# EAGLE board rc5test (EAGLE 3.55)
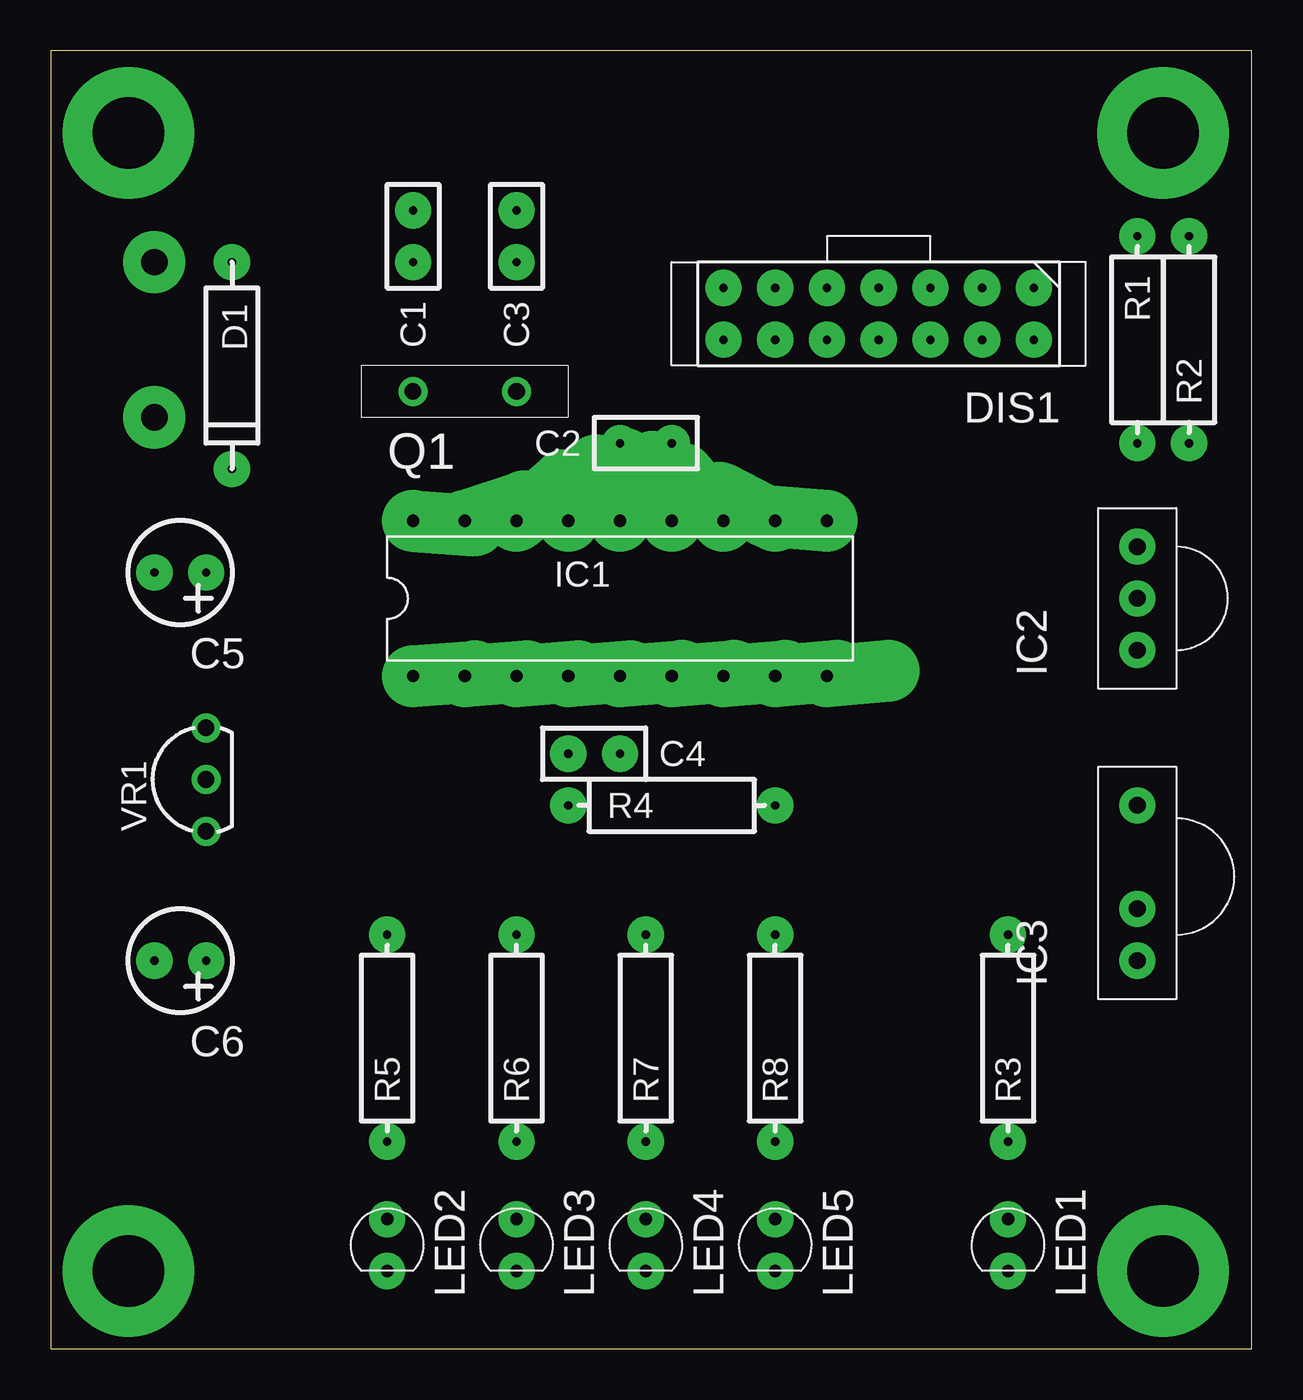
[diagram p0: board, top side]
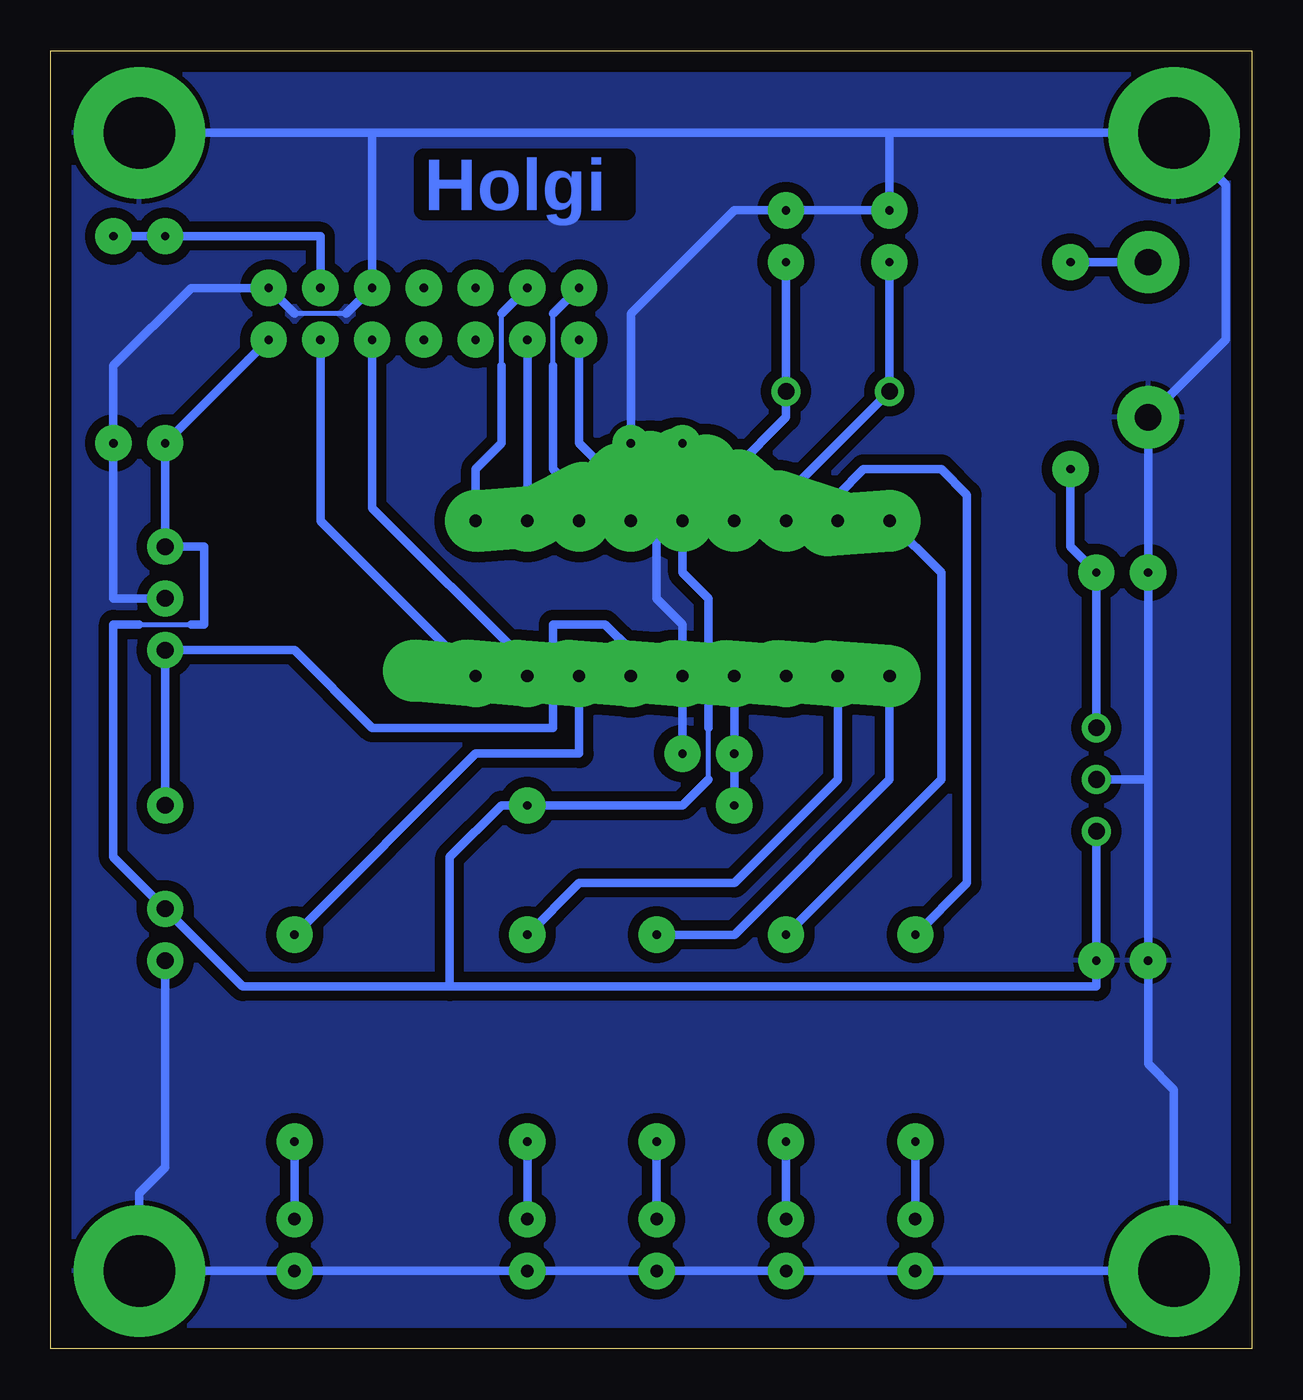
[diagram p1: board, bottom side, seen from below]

Size 58.95 x 63.71 mm. Coordinates in mm from the lower left corner, seen from the top.
Outline: 0,0 58.95,0 58.95,63.71 0,63.71 0,0
Copper layers used: Bottom

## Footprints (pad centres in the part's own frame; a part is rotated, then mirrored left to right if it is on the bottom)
RM2,5 = drill 0.406 pad 1.778 round:  0,0;  2.54,0
KO01 = drill 0.406 pad 1.778 round:  0,0;  2.54,0
O04 = drill 0.406 pad 1.778 round:  0,0;  10.16,0
7 = drill 0.406 pad 1.778 round:  0,0;  2.54,0;  5.08,0;  7.62,0;  10.16,0;  10.16,2.54;  7.62,2.54;  5.08,2.54;  2.54,2.54;  0,2.54;  12.7,0;  12.7,2.54;  15.24,0;  15.24,2.54
L-18B = drill 0.61 pad 3.048 offset:  0,0;  2.54,0;  15.24,0;  17.78,0;  5.08,0;  7.62,0;  12.7,0;  10.16,0;  20.32,0;  20.32,7.62;  17.78,7.62;  15.24,7.62;  12.7,7.62;  10.16,7.62;  7.62,7.62;  5.08,7.62;  2.54,7.62;  0,7.62
OP1836 = drill 0.813 pad 1.778 round:  0,0;  2.54,0;  5.08,0
REC = drill 0.813 pad 1.778 round:  0,0;  2.54,0;  7.62,0
D_3MM = drill 0.61 pad 1.778 round:  0,0;  2.54,0
GEL = drill 1.295 pad 3.048 round:  0,0
ARZ_ST = drill 0.813 pad 1.422 round:  0,0;  5.08,0
S04 = drill 0.406 pad 1.778 round:  0,0;  10.16,0
HRUNG = drill 3.505 pad 6.452 round:  0,0
92-B = drill 0.813 pad 1.422 round:  -2.54,0;  2.54,0;  0,0

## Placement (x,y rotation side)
C1  27p  [RM2,5]  17.78,55.88 270 top
C2  100n  [RM2,5]  30.48,44.45 180 top
C3  27p  [RM2,5]  22.86,55.88 270 top
C4  100n  [RM2,5]  25.4,29.21 0 top
C5  100u  [KO01]  7.62,38.1 180 top
C6  47u  [KO01]  7.62,19.05 180 top
D1  1N4148  [O04]  8.89,53.34 270 top
DIS1  LCD  [7]  48.26,52.07 180 top
IC1  16F84P  [L-18B]  17.78,33.02 0 top
IC2  TSOP1836  [OP1836]  53.34,34.29 90 top
IC3  TSOP1736  [REC]  53.34,19.05 90 top
LED1  Receive  [D_3MM]  46.99,6.35 270 top
LED2  COM4  [D_3MM]  16.51,6.35 270 top
LED3  COM5  [D_3MM]  22.86,6.35 270 top
LED4  COM6  [D_3MM]  29.21,6.35 270 top
LED5  COM7  [D_3MM]  35.56,6.35 270 top
N1  +  [GEL]  5.08,53.34 0 top
N2  -  [GEL]  5.08,45.72 0 top
Q1  4MHz  [ARZ_ST]  17.78,46.99 0 top
R1  12k  [S04]  53.34,54.61 270 top
R2  1k  [S04]  55.88,44.45 90 top
R3  270  [S04]  46.99,10.16 90 top
R4  10k  [S04]  25.4,26.67 0 top
R5  270  [S04]  16.51,10.16 90 top
R6  270  [S04]  22.86,10.16 90 top
R7  270  [S04]  29.21,10.16 90 top
R8  270  [S04]  35.56,10.16 90 top
U$15  BOHRUNG  [HRUNG]  54.61,59.69 0 top
U$16  BOHRUNG  [HRUNG]  54.61,3.81 0 top
U$26  BOHRUNG  [HRUNG]  3.81,3.81 0 top
U$27  BOHRUNG  [HRUNG]  3.81,59.69 0 top
VR1  78L05  [92-B]  7.62,27.94 90 top

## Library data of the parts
C1-C5 D1 DIS1 LED1-LED5 R3 R5-R8 = holg_plt
C6 N1 N2 R1 R2 R4 U$15 U$16 U$26 U$27 VR1 = holgnorm
IC1 = PIC
IC2 IC3 = ic_holg
Q1 = bts

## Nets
+5V: C2. C6. DIS1. IC1. IC2. IC3. R1. R4. VR1.
+UB: C5. D1. VR1.
GND: C1. C2. C3. C4. C5. C6. DIS1. IC1. IC2. IC3. LED1. LED2. LED3. LED4. LED5. N2. R2. U$15. U$16. U$26. U$27. VR1.
N$1: C1. IC1. Q1.
N$2: D1. N1.
N$3: C3. IC1. Q1.
N$4: LED1. R3.
N$5: C4. IC1. R4.
N$6: IC1. R3.
N$7: DIS1. IC1.
N$8: DIS1. IC1.
N$9: IC1. IC2. IC3.
N$10: DIS1. IC1.
N$11: DIS1. IC1.
N$12: IC1. R5.
N$13: IC1. R6.
N$14: IC1. R7.
N$15: IC1. R8.
N$16: LED5. R8.
N$17: LED4. R7.
N$18: LED3. R6.
N$19: LED2. R5.
N$22: DIS1. R1. R2.
N$23: DIS1. IC1.
N$24: DIS1. IC1.

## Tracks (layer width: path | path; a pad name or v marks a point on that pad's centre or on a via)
+5V
  Bottom 0.254: 26.67,27.94 26.67,30.48 | 54.61,35.56 52.07,35.56
  Bottom 0.406: 7.62,19.05 7.62,25.4 7.62,19.05 | C2. 27.94,40.64 27.94,38.1 26.67,36.83 26.67,30.48 | 48.26,49.53 R1. IC2. 51.44,39.37 51.44,35.56 52.07,35.56 | 39.37,17.78 39.37,24.13 36.83,26.67 R4. 27.94,26.67 26.67,27.94 | 39.37,17.78 49.53,17.78 53.34,21.59 55.88,24.13 55.88,35.56 54.61,35.56 | 7.62,19.05 7.62,17.78 39.37,17.78
+UB
  Bottom 0.406: 7.62,30.48 7.62,38.1 8.89,39.37 D1.
GND
  Bottom 0.254: 44.45,50.8 46.99,50.8
  Bottom 0.406: C4. 27.94,33.02 27.94,35.56 29.21,36.83 29.21,43.18 30.48,44.45 30.48,50.8 25.4,55.88 22.86,55.88 17.78,55.88 17.78,59.69 | 5.08,27.94 C5. N2. 1.27,49.53 1.27,57.15 U$27. 17.78,59.69 | 5.08,27.94 VR1. | 5.08,27.94 C6. 5.08,13.97 3.81,12.7 U$26. LED2. LED3. LED4. LED5. LED1. U$16. 54.61,7.62 53.34,8.89 53.34,19.05 | 53.34,36.83 55.88,36.83 55.88,44.45 55.88,48.26 52.07,52.07 48.26,52.07 46.99,50.8 | 44.45,50.8 43.18,52.07 43.18,59.69 | 43.18,59.69 U$15. | 17.78,59.69 43.18,59.69
  pour Bottom (isolate 0.508): 0.64,62.87 0.64,0.64 58.42,0.64 58.42,62.87
N$1
  Bottom 0.406: C1. 17.78,46.99 22.86,41.91 22.86,40.64
N$2
  Bottom 0.406: N1. 8.89,53.34
N$3
  Bottom 0.406: 25.4,40.64 25.4,43.18 22.86,45.72 Q1. C3.
N$4
  Bottom 0.406: 46.99,6.35 46.99,10.16
N$5
  Bottom 0.406: 25.4,33.02 25.4,29.21 25.4,26.67
N$6
  Bottom 0.406: 33.02,33.02 33.02,29.21 38.1,29.21 R3.
N$7
  Bottom 0.406: 30.48,40.64 30.48,41.91 33.02,44.45 DIS1.
N$8
  Bottom 0.254: 34.29,48.26 34.29,50.8
  Bottom 0.406: 33.02,40.64 33.02,41.91 34.29,43.18 34.29,48.26 | 34.29,50.8 33.02,52.07
N$9
  Bottom 0.406: 30.48,33.02 30.48,34.29 31.75,35.56 34.29,35.56 34.29,30.48 43.18,30.48 46.99,34.29 53.34,34.29 IC3.
N$10
  Bottom 0.406: 35.56,40.64 35.56,49.53
N$11
  Bottom 0.254: 36.83,48.26 36.83,50.8
  Bottom 0.406: 36.83,50.8 35.56,52.07 | 38.1,40.64 38.1,43.18 36.83,44.45 36.83,48.26
N$12
  Bottom 0.406: 20.32,40.64 20.32,41.91 19.05,43.18 15.24,43.18 13.97,41.91 13.97,22.86 R5.
N$13
  Bottom 0.406: IC1. 15.24,38.1 15.24,27.94 R6.
N$14
  Bottom 0.406: R7. 25.4,20.32 17.78,27.94 17.78,33.02
N$15
  Bottom 0.406: R8. 33.02,22.86 25.4,22.86 20.32,27.94 20.32,33.02
N$16
  Bottom 0.406: 35.56,6.35 35.56,10.16
N$17
  Bottom 0.406: 29.21,6.35 29.21,10.16
N$18
  Bottom 0.406: 22.86,6.35 22.86,10.16
N$19
  Bottom 0.406: 16.51,6.35 16.51,10.16
N$22
  Bottom 0.406: R2. 53.34,54.61 45.72,54.61 45.72,52.07
N$23
  Bottom 0.406: 38.1,33.02 45.72,40.64 45.72,49.53
N$24
  Bottom 0.406: 35.56,33.02 35.56,33.66 43.18,41.27 43.18,49.53

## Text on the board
Bottom: Holgi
